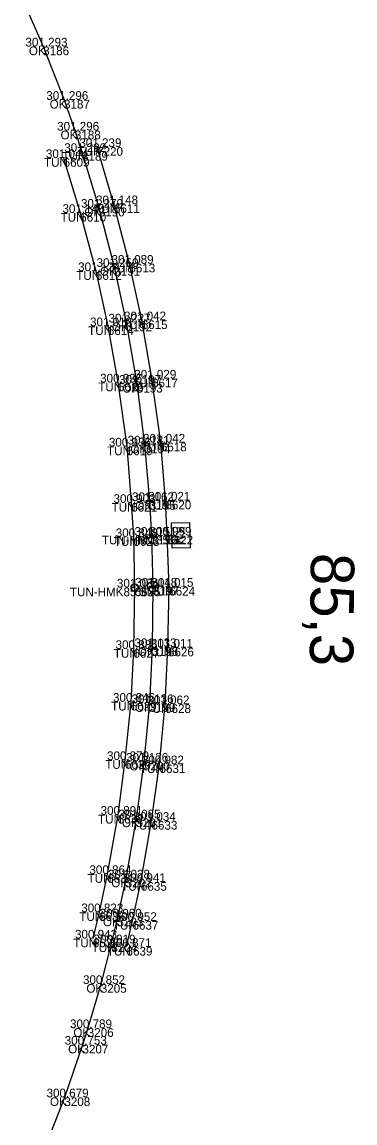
# Model space of a CAD drawing. Extents: x -621782 to -610392, y -1141853 to -1122321.
# Drawn here: x -612824.8 to -612778.8, y -1134042.7 to -1133890.8 of the extents above; entities that cross this region are included whole.
import ezdxf

# ---------------------------------------------------------------- set-up
doc = ezdxf.new("R2010")
doc.units = 0
for name, color, linetype in [('Vrstva 1', 7, 'Continuous'), ('Vrstva 22', 7, 'Continuous'), ('Vrstva 60', 7, 'Continuous'), ('Vrstva 61', 7, 'Continuous'), ('Vrstva 62', 7, 'Continuous'), ('Vrstva 7', 7, 'Continuous')]:
    doc.layers.add(name, color=color, linetype=linetype)

msp = doc.modelspace()

# ---------------------------------------------------------------- linework, layer by layer
at = {"layer": 'Vrstva 1'}
msp.add_lwpolyline([(-612824.78, -1133887.42), (-612821.85, -1133894.17), (-612818.98, -1133901.53), (-612817.48, -1133905.77), (-612816.5, -1133908.72), (-612814.18, -1133916.41), (-612812.04, -1133924.58), (-612810.39, -1133932.24), (-612808.93, -1133940.7), (-612807.85, -1133949.07), (-612807.16, -1133956.87), (-612806.89, -1133961.66), (-612806.71, -1133968.67), (-612806.8, -1133977.02), (-612807.2, -1133984.74), (-612807.96, -1133992.82), (-612809, -1134000.65), (-612810.47, -1134008.93), (-612811.61, -1134014.31), (-612812.45, -1134017.88), (-612813.91, -1134023.49), (-612815.7, -1134029.58), (-612816.43, -1134031.86), (-612818.93, -1134039.12), (-612821.66, -1134046.19)], dxfattribs=at)
at = {"layer": 'Vrstva 22'}
for points in [[(-612810.35, -1134018.37), (-612809.53, -1134014.79), (-612808.37, -1134009.42), (-612806.91, -1134000.99), (-612805.8, -1133993.18), (-612805.03, -1133984.9), (-612804.63, -1133977.09), (-612804.46, -1133968.7), (-612804.74, -1133961.64), (-612804.99, -1133956.81), (-612805.62, -1133948.81), (-612806.84, -1133939.98), (-612808.25, -1133931.94), (-612809.96, -1133924.14), (-612812.1, -1133915.93), (-612814.41, -1133908.04)], [(-612819.03, -1133909.56), (-612816.74, -1133917.13), (-612814.58, -1133925.16), (-612812.94, -1133932.76), (-612811.55, -1133940.52), (-612810.33, -1133949.35), (-612809.7, -1133957.13), (-612809.39, -1133961.85), (-612809.23, -1133968.8), (-612809.4, -1133977.28), (-612809.77, -1133984.56), (-612810.58, -1133992.6), (-612811.57, -1134000.15), (-612813.02, -1134008.32), (-612814.15, -1134013.59), (-612815.01, -1134017.22)]]:
    msp.add_lwpolyline(points, dxfattribs=at)
at = {"layer": 'Vrstva 60'}
for p, q in [((-612821.85, -1133894.17), (-612821.85, -1133894.17)), ((-612818.98, -1133901.53), (-612818.98, -1133901.53)), ((-612817.48, -1133905.77), (-612817.48, -1133905.77)), ((-612816.5, -1133908.72), (-612816.5, -1133908.72)), ((-612814.41, -1133908.04), (-612814.41, -1133908.04)), ((-612819.03, -1133909.56), (-612819.03, -1133909.56)), ((-612814.18, -1133916.41), (-612814.18, -1133916.41)), ((-612812.1, -1133915.93), (-612812.1, -1133915.93)), ((-612816.74, -1133917.13), (-612816.74, -1133917.13)), ((-612812.04, -1133924.58), (-612812.04, -1133924.58)), ((-612809.96, -1133924.14), (-612809.96, -1133924.14)), ((-612814.58, -1133925.16), (-612814.58, -1133925.16)), ((-612810.39, -1133932.24), (-612810.39, -1133932.24)), ((-612808.25, -1133931.94), (-612808.25, -1133931.94)), ((-612812.94, -1133932.76), (-612812.94, -1133932.76)), ((-612811.55, -1133940.52), (-612811.55, -1133940.52)), ((-612808.93, -1133940.7), (-612808.93, -1133940.7)), ((-612806.84, -1133939.98), (-612806.84, -1133939.98)), ((-612805.62, -1133948.81), (-612805.62, -1133948.81)), ((-612810.33, -1133949.35), (-612810.33, -1133949.35)), ((-612807.85, -1133949.07), (-612807.85, -1133949.07)), ((-612809.7, -1133957.13), (-612809.7, -1133957.13)), ((-612807.16, -1133956.87), (-612807.16, -1133956.87)), ((-612804.99, -1133956.81), (-612804.99, -1133956.81)), ((-612809.39, -1133961.85), (-612809.39, -1133961.85)), ((-612806.89, -1133961.66), (-612806.89, -1133961.66)), ((-612804.74, -1133961.64), (-612804.74, -1133961.64)), ((-612806.71, -1133968.67), (-612806.71, -1133968.67)), ((-612804.46, -1133968.7), (-612804.46, -1133968.7)), ((-612809.23, -1133968.8), (-612809.23, -1133968.8)), ((-612809.4, -1133977.28), (-612809.4, -1133977.28)), ((-612806.8, -1133977.02), (-612806.8, -1133977.02)), ((-612804.63, -1133977.09), (-612804.63, -1133977.09)), ((-612809.77, -1133984.56), (-612809.77, -1133984.56)), ((-612807.2, -1133984.74), (-612807.2, -1133984.74)), ((-612805.03, -1133984.9), (-612805.03, -1133984.9)), ((-612810.58, -1133992.6), (-612810.58, -1133992.6)), ((-612807.96, -1133992.82), (-612807.96, -1133992.82)), ((-612805.8, -1133993.18), (-612805.8, -1133993.18)), ((-612811.57, -1134000.15), (-612811.57, -1134000.15)), ((-612809, -1134000.65), (-612809, -1134000.65)), ((-612806.91, -1134000.99), (-612806.91, -1134000.99)), ((-612813.02, -1134008.32), (-612813.02, -1134008.32)), ((-612810.47, -1134008.93), (-612810.47, -1134008.93)), ((-612808.37, -1134009.42), (-612808.37, -1134009.42)), ((-612814.15, -1134013.59), (-612814.15, -1134013.59)), ((-612811.61, -1134014.31), (-612811.61, -1134014.31)), ((-612809.53, -1134014.79), (-612809.53, -1134014.79)), ((-612815.01, -1134017.22), (-612815.01, -1134017.22)), ((-612812.45, -1134017.88), (-612812.45, -1134017.88)), ((-612810.35, -1134018.37), (-612810.35, -1134018.37)), ((-612813.91, -1134023.49), (-612813.91, -1134023.49)), ((-612815.7, -1134029.58), (-612815.7, -1134029.58)), ((-612816.43, -1134031.86), (-612816.43, -1134031.86)), ((-612818.93, -1134039.12), (-612818.93, -1134039.12))]:
    msp.add_line(p, q, dxfattribs=at)
at = {"layer": 'Vrstva 7'}
for p, q in [((-612802.27, -1133960.56), (-612803.52, -1133960.59)), ((-612802.8, -1133960.88), (-612803.5, -1133961.43)), ((-612802.25, -1133961.4), (-612803.11, -1133960.58)), ((-612804.74, -1133961.64), (-612804.11, -1133961.63)), ((-612809.23, -1133968.75), (-612809.23, -1133968.85))]:
    msp.add_line(p, q, dxfattribs=at)
msp.add_lwpolyline([(-612804.16, -1133959.89), (-612801.68, -1133959.82), (-612801.59, -1133963.31), (-612804.07, -1133963.37)], close=True, dxfattribs=at)
msp.add_lwpolyline([(-612803.49, -1133961.84), (-612802.24, -1133961.81), (-612803.48, -1133962.32), (-612802.22, -1133962.76), (-612803.47, -1133962.79)], dxfattribs=at)
for centre, radius in [((-612809.23, -1133968.8), 0.5), ((-612806.71, -1133968.67), 0.75)]:
    msp.add_circle(centre, radius, dxfattribs=at)

# ---------------------------------------------------------------- texts
at = {"layer": 'Vrstva 60'}
for s, p in [('3186', (-612821.85, -1133895.37)), ('3187', (-612818.98, -1133902.73)), ('3188', (-612817.48, -1133906.97)), ('3189', (-612816.5, -1133909.92)), ('7220', (-612814.41, -1133909.24)), ('6609', (-612819.03, -1133910.76)), ('3190', (-612814.18, -1133917.61)), ('6611', (-612812.1, -1133917.13)), ('6610', (-612816.74, -1133918.33)), ('3191', (-612812.04, -1133925.78)), ('6613', (-612809.96, -1133925.33)), ('6612', (-612814.58, -1133926.36)), ('3192', (-612810.39, -1133933.44)), ('6615', (-612808.25, -1133933.14)), ('6614', (-612812.94, -1133933.96)), ('6616', (-612811.55, -1133941.72)), ('3193', (-612808.93, -1133941.9)), ('6617', (-612806.84, -1133941.18)), ('6618', (-612805.62, -1133950.01)), ('6619', (-612810.33, -1133950.55)), ('3194', (-612807.85, -1133950.27)), ('6621', (-612809.7, -1133958.33)), ('3195', (-612807.16, -1133958.07)), ('6620', (-612804.99, -1133958.01)), ('6623', (-612809.39, -1133963.05)), ('3196', (-612806.89, -1133962.86)), ('6622', (-612804.74, -1133962.84)), ('3197', (-612806.71, -1133969.87)), ('6624', (-612804.46, -1133969.9)), ('6625', (-612809.23, -1133970)), ('6627', (-612809.4, -1133978.48)), ('3198', (-612806.8, -1133978.22)), ('6626', (-612804.63, -1133978.29)), ('6629', (-612809.77, -1133985.76)), ('3199', (-612807.2, -1133985.94)), ('6628', (-612805.03, -1133986.1)), ('6630', (-612810.58, -1133993.8)), ('3200', (-612807.96, -1133994.02)), ('6631', (-612805.8, -1133994.38)), ('6632', (-612811.57, -1134001.35)), ('3201', (-612809, -1134001.85)), ('6633', (-612806.91, -1134002.19)), ('6634', (-612813.02, -1134009.52)), ('3202', (-612810.47, -1134010.13)), ('6635', (-612808.37, -1134010.62)), ('6636', (-612814.15, -1134014.79)), ('3203', (-612811.61, -1134015.52)), ('6637', (-612809.53, -1134015.99)), ('6638', (-612815.01, -1134018.42)), ('3204', (-612812.45, -1134019.08)), ('6639', (-612810.35, -1134019.57)), ('3205', (-612813.91, -1134024.69)), ('3206', (-612815.7, -1134030.78)), ('3207', (-612816.43, -1134033.06)), ('3208', (-612818.93, -1134040.32))]:
    msp.add_text(s, height=1.2, dxfattribs=at).set_placement(p)
at = {"layer": 'Vrstva 61'}
for s, p in [('301.293', (-612824.3, -1133894.17)), ('301.296', (-612821.43, -1133901.53)), ('301.296', (-612819.93, -1133905.77)), ('301.292', (-612818.95, -1133908.72)), ('301.239', (-612816.86, -1133908.04)), ('301.044', (-612821.48, -1133909.56)), ('301.279', (-612816.64, -1133916.41)), ('301.148', (-612814.56, -1133915.93)), ('301.140', (-612819.19, -1133917.13)), ('301.089', (-612812.42, -1133924.14)), ('301.124', (-612817.03, -1133925.16)), ('301.259', (-612814.49, -1133924.58)), ('301.042', (-612810.7, -1133931.94)), ('301.012', (-612815.39, -1133932.76)), ('301.227', (-612812.84, -1133932.24)), ('300.936', (-612814, -1133940.52)), ('301.197', (-612811.38, -1133940.7)), ('301.029', (-612809.29, -1133939.98)), ('300.936', (-612812.79, -1133949.35)), ('301.181', (-612810.2, -1133949.07)), ('301.042', (-612808.07, -1133948.81)), ('300.903', (-612812.15, -1133957.13)), ('301.162', (-612809.61, -1133956.87)), ('301.021', (-612807.35, -1133956.81)), ('300.848', (-612811.84, -1133961.85)), ('301.151', (-612809.25, -1133961.66)), ('300.999', (-612807.19, -1133961.64)), ('301.084', (-612811.68, -1133968.8)), ('301.148', (-612809.16, -1133968.67)), ('301.015', (-612806.92, -1133968.7)), ('300.885', (-612811.86, -1133977.28)), ('301.133', (-612809.25, -1133977.02)), ('301.011', (-612806.99, -1133977.09)), ('300.846', (-612812.22, -1133984.56)), ('301.136', (-612809.66, -1133984.74)), ('301.062', (-612807.47, -1133984.9)), ('300.879', (-612813.04, -1133992.6)), ('301.126', (-612810.41, -1133992.82)), ('300.982', (-612808.24, -1133993.18)), ('300.891', (-612813.93, -1134000.15)), ('301.085', (-612811.46, -1134000.65)), ('301.034', (-612809.36, -1134000.99)), ('300.864', (-612815.47, -1134008.32)), ('301.028', (-612812.92, -1134008.93)), ('300.941', (-612810.73, -1134009.42)), ('300.823', (-612816.6, -1134013.59)), ('300.960', (-612814.06, -1134014.31)), ('300.952', (-612811.98, -1134014.79)), ('300.943', (-612817.46, -1134017.22)), ('300.919', (-612814.91, -1134017.88)), ('300.871', (-612812.71, -1134018.37)), ('300.852', (-612816.36, -1134023.49)), ('300.789', (-612818.16, -1134029.58)), ('300.753', (-612818.88, -1134031.86)), ('300.679', (-612821.39, -1134039.12))]:
    msp.add_text(s, height=1.2, dxfattribs=at).set_placement(p)
at = {"layer": 'Vrstva 62'}
for s, p in [('OK', (-612823.83, -1133895.37)), ('OK', (-612820.96, -1133902.73)), ('OK', (-612819.46, -1133906.97)), ('TUN', (-612819.21, -1133909.92)), ('TUN', (-612817.12, -1133909.24)), ('TUN', (-612821.74, -1133910.76)), ('OK', (-612816.17, -1133917.61)), ('TUN', (-612814.81, -1133917.13)), ('TUN', (-612819.45, -1133918.33)), ('OK', (-612814.02, -1133925.78)), ('TUN', (-612812.67, -1133925.33)), ('TUN', (-612817.29, -1133926.36)), ('OK', (-612812.38, -1133933.44)), ('TUN', (-612810.96, -1133933.14)), ('TUN', (-612815.65, -1133933.96)), ('TUN', (-612814.26, -1133941.72)), ('OK', (-612810.91, -1133941.9)), ('TUN', (-612809.55, -1133941.18)), ('TUN', (-612808.33, -1133950.01)), ('TUN', (-612813.04, -1133950.55)), ('OK', (-612809.83, -1133950.27)), ('TUN', (-612812.41, -1133958.33)), ('OK', (-612809.14, -1133958.07)), ('TUN', (-612807.7, -1133958.01)), ('TUN-HMC85.3', (-612813.76, -1133962.84)), ('TUN', (-612812.1, -1133963.05)), ('HM', (-612808.92, -1133962.86)), ('HM', (-612808.74, -1133969.87)), ('TUN', (-612807.17, -1133969.9)), ('TUN-HMK85.3', (-612818.17, -1133970)), ('TUN', (-612812.11, -1133978.48)), ('OK', (-612808.79, -1133978.22)), ('TUN', (-612807.34, -1133978.29)), ('TUN', (-612812.48, -1133985.76)), ('OK', (-612809.19, -1133985.94)), ('TUN', (-612807.73, -1133986.1)), ('TUN', (-612813.29, -1133993.8)), ('OK', (-612809.94, -1133994.02)), ('TUN', (-612808.5, -1133994.38)), ('TUN', (-612814.28, -1134001.35)), ('OK', (-612810.98, -1134001.85)), ('TUN', (-612809.62, -1134002.19)), ('TUN', (-612815.73, -1134009.52)), ('OK', (-612812.45, -1134010.13)), ('TUN', (-612811.08, -1134010.62)), ('TUN', (-612816.86, -1134014.79)), ('OK', (-612813.6, -1134015.52)), ('TUN', (-612812.24, -1134015.99)), ('TUN', (-612817.71, -1134018.42)), ('TUN', (-612815.16, -1134019.08)), ('TUN', (-612813.06, -1134019.57)), ('OK', (-612815.89, -1134024.69)), ('OK', (-612817.69, -1134030.78)), ('OK', (-612818.41, -1134033.06)), ('OK', (-612820.92, -1134040.32))]:
    msp.add_text(s, height=1.2, dxfattribs=at).set_placement(p)
at = {"layer": 'Vrstva 7'}
msp.add_text('85,3', height=6, rotation=269.3684, dxfattribs=at).set_placement((-612784.9, -1133964))

doc.saveas('drawing.dxf')
